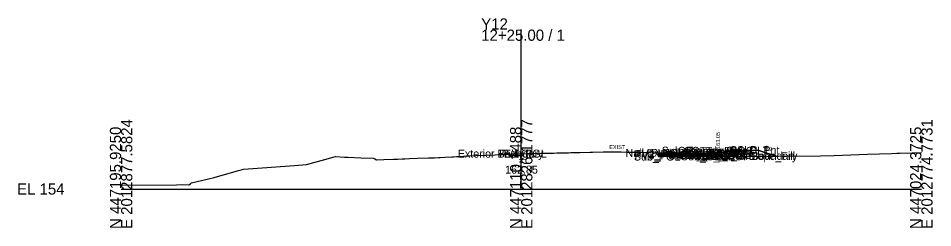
# Model space of a CAD drawing. Extents: x -26 to 1203, y -10 to 9542.
# Drawn here: x -25.7 to 202.8, y 4490.3 to 4542.7 of the extents above; entities that cross this region are included whole.
import ezdxf

# ---------------------------------------------------------------- set-up
doc = ezdxf.new("R2010")
doc.units = 0
for name, color, linetype in [('Default', 7, 'Continuous'), ('Exist Cross Section Cell', 7, 'Continuous'), ('Exist XS Center Line Elevation Label', 7, 'Continuous'), ('Exist XS Ground Line', 7, 'Continuous'), ('Prop CMT Conc Surface', 7, 'Continuous'), ('Prop CMT Concrete Structures', 7, 'Continuous'), ('Prop CMT Pvmt Course 1', 7, 'Continuous'), ('Prop CMT Pvmt Course 1 CG', 7, 'Continuous'), ('Prop CMT Pvmt Course 2', 7, 'Continuous'), ('Prop CMT Pvmt Course 3', 7, 'Continuous'), ('Prop CMT Pvmt Surface', 7, 'Continuous'), ('Prop CMT Slope Grass', 7, 'Continuous'), ('Prop CMT Subgrade Earthwork', 7, 'Continuous'), ('Prop XS Earthwork Shape', 7, 'Continuous'), ('Prop XS Hydro Elevations', 7, 'Continuous'), ('Prop XS SE Text', 7, 'Continuous'), ('Prop XS Side Slope Text', 7, 'Continuous'), ('Scratch_Level_0', 7, 'Continuous')]:
    doc.layers.add(name, color=color, linetype=linetype)

msp = doc.modelspace()

# ---------------------------------------------------------------- linework, layer by layer
at = {"layer": 'Exist Cross Section Cell'}
for p, q in [((100, 4500), (100, 4539.91)), ((0, 4500), (100, 4500)), ((100, 4500), (200, 4500))]:
    msp.add_line(p, q, dxfattribs=at)
at = {"layer": 'Exist XS Ground Line'}
msp.add_lwpolyline([(0, 4500.95), (13.82, 4501.09), (15.39, 4501.11), (16.89, 4501.03), (17.32, 4501.32), (17.62, 4501.54), (23.3, 4502.87), (29.36, 4504.62), (30.04, 4504.81), (30.61, 4505), (43.37, 4505.92), (46.33, 4506.17), (50.92, 4507.4), (53.59, 4508.1), (55.84, 4508), (56.7, 4507.96), (59.94, 4507.83), (63.05, 4507.71), (63.39, 4507.54), (63.83, 4507.32), (65.68, 4507.36), (68.05, 4507.46), (69.12, 4507.51), (70.26, 4507.55), (70.94, 4507.58), (72.12, 4507.62), (74.09, 4507.69), (76.79, 4507.78), (78.31, 4507.82), (79.35, 4507.89), (79.73, 4507.91), (80.9, 4507.97), (82.62, 4508.06), (83.06, 4508.08), (83.79, 4508.12), (84.9, 4508.17), (85.55, 4508.2), (88.56, 4508.35), (91.35, 4508.48), (93.48, 4508.58), (94.25, 4508.61), (95.8, 4508.67), (97.16, 4508.75), (97.59, 4508.77), (98.35, 4508.79), (99.46, 4508.83), (100.13, 4508.85), (101.29, 4508.88), (103.25, 4508.91), (104.93, 4508.95), (105.95, 4508.97), (106.76, 4508.99), (108.12, 4509.01), (108.87, 4509.03), (110, 4509.06), (111.78, 4509.1), (112.44, 4509.12), (112.88, 4509.13), (114.68, 4509.18), (117.24, 4509.23), (117.81, 4509.24), (120.49, 4509.29), (122.67, 4509.31), (123.43, 4509.31), (123.85, 4509.3), (124.95, 4509.28), (126.32, 4509.25), (127.53, 4509.23), (129.24, 4509.2), (130.43, 4509.17), (132.4, 4509.11), (134.22, 4509.05), (135.88, 4508.97), (136.62, 4509.41), (137.25, 4509.31), (137.84, 4509.22), (138.14, 4509.17), (140.34, 4508.87), (144.21, 4508.47), (147.2, 4508.21), (148.53, 4508.15), (148.95, 4508.14), (149.27, 4508.14), (153.82, 4508.16), (174.82, 4508.31), (178.17, 4508.41), (186.52, 4508.7), (192.55, 4508.89), (193.84, 4508.94), (194.61, 4508.98), (197.69, 4509.05), (200, 4509.13)], dxfattribs=at)
at = {"layer": 'Prop CMT Conc Surface'}
msp.add_lwpolyline([(147.17, 4509.12), (149.17, 4509.05), (149.17, 4509.55), (149.67, 4509.55)], dxfattribs=at)
at = {"layer": 'Prop CMT Concrete Structures'}
for points in [[(147.17, 4509.12), (149.17, 4509.05), (149.17, 4509.55), (149.67, 4509.55)], [(149.67, 4509.55), (149.67, 4508.55), (147.17, 4508.53)], [(147.17, 4508.53), (147.17, 4509.12)]]:
    msp.add_lwpolyline(points, dxfattribs=at)
at = {"layer": 'Prop CMT Pvmt Course 1'}
for points in [[(134.35, 4509.04), (147.17, 4509.12)], [(134.35, 4509.04), (134.35, 4509.04)], [(134.35, 4508.79), (134.35, 4509.04)], [(147.17, 4509.12), (147.17, 4508.87)], [(100, 4508.86), (100, 4508.86)], [(147.17, 4508.87), (134.35, 4508.79)]]:
    msp.add_lwpolyline(points, dxfattribs=at)
at = {"layer": 'Prop CMT Pvmt Course 1 CG'}
for points in [[(147.17, 4508.53), (150.17, 4508.55), (150.5, 4508.22)], [(147.17, 4508.2), (147.17, 4508.53)], [(150.5, 4508.22), (147.17, 4508.2)]]:
    msp.add_lwpolyline(points, dxfattribs=at)
at = {"layer": 'Prop CMT Pvmt Course 2'}
for points in [[(134.35, 4508.79), (147.17, 4508.87)], [(134.35, 4508.46), (134.35, 4508.79)], [(147.17, 4508.53), (134.35, 4508.46)], [(147.17, 4508.87), (147.17, 4508.53)]]:
    msp.add_lwpolyline(points, dxfattribs=at)
at = {"layer": 'Prop CMT Pvmt Course 3'}
for points in [[(134.35, 4508.46), (147.17, 4508.53)], [(134.35, 4508.13), (134.35, 4508.46)], [(147.17, 4508.2), (134.35, 4508.13)], [(147.17, 4508.53), (147.17, 4508.2)]]:
    msp.add_lwpolyline(points, dxfattribs=at)
at = {"layer": 'Prop CMT Pvmt Surface'}
msp.add_lwpolyline([(134.35, 4509.04), (147.17, 4509.12)], dxfattribs=at)
at = {"layer": 'Prop CMT Slope Grass'}
msp.add_lwpolyline([(149.67, 4509.55), (159.17, 4509.74), (163.68, 4508.23)], dxfattribs=at)
at = {"layer": 'Prop CMT Subgrade Earthwork'}
for points in [[(134.35, 4508.13), (134.35, 4509.04)], [(147.17, 4508.2), (150.5, 4508.22), (151.87, 4509.59)], [(134.35, 4508.13), (147.17, 4508.2)], [(147.17, 4508.2), (134.35, 4508.13)]]:
    msp.add_lwpolyline(points, dxfattribs=at)
at = {"layer": 'Prop XS Earthwork Shape'}
for points in [[(134.35, 4509.04), (135.88, 4508.97), (136.01, 4509.05), (138.9, 4509.07), (140.34, 4508.87), (144.21, 4508.47), (147.2, 4508.21), (147.43, 4508.2), (147.17, 4508.2), (134.35, 4508.13)], [(137.25, 4509.31), (137.84, 4509.22), (138.14, 4509.17), (138.9, 4509.07), (136.01, 4509.05), (136.62, 4509.41)], [(149.27, 4508.14), (153.82, 4508.16), (163.68, 4508.23), (159.17, 4509.74), (151.87, 4509.59), (150.5, 4508.22), (147.43, 4508.2), (148.53, 4508.15), (148.95, 4508.14)]]:
    msp.add_lwpolyline(points, close=True, dxfattribs=at)

# ---------------------------------------------------------------- texts
at = {"layer": 'Default'}
msp.add_text('-', height=0.0001, dxfattribs=at).set_placement((0, 4500))
at = {"layer": 'Exist Cross Section Cell'}
for s, p in [('Y12', (90, 4539.91)), ('12+25.00 / 1', (90, 4537.11)), ('EL 154', (-26, 4498.6))]:
    msp.add_text(s, height=2.8, dxfattribs=at).set_placement(p)
for s, p in [('E 2012877.5824', (2.8, 4490)), ('E 2012826.1777', (102.8, 4490)), ('E 2012774.7731', (202.8, 4490)), ('N 447195.9250', (0, 4490)), ('N 447110.1488', (100, 4490)), ('N 447024.3725', (200, 4490))]:
    msp.add_text(s, height=2.8, rotation=90, dxfattribs=at).set_placement(p)
at = {"layer": 'Exist XS Center Line Elevation Label'}
msp.add_text('162.85', height=2, dxfattribs=at).set_placement((95.98, 4503.85))
at = {"layer": 'Prop XS Hydro Elevations'}
msp.add_text('163.05', height=1, rotation=90, dxfattribs=at).set_placement((149.67, 4510.05))
at = {"layer": 'Prop XS SE Text'}
msp.add_text('EXIST', height=1, rotation=0.314, dxfattribs=at).set_placement((122, 4509.98))
at = {"layer": 'Prop XS Side Slope Text'}
msp.add_text('3:1', height=1, rotation=341.5647, dxfattribs=at).set_placement((160.81, 4509.98))
at = {"layer": 'Scratch_Level_0'}
for s, p in [('Exterior Boundary', (84.14, 4507.86)), ('PV1_PGL', (94.47, 4507.86)), ('EX CL', (95.67, 4507.86)), ('Null Ex EOP', (126.05, 4508.04)), ('Sub_PGL', (128.16, 4507.13)), ('PV2_PGL', (128.26, 4507.79)), ('PV3_PGL', (128.26, 4507.46)), ('PV1', (132.43, 4508.04)), ('Sub_Trench_Out_DLT', (135.13, 4508.59)), ('CG_Top_Face', (139.12, 4508.55)), ('CG1_Shelf_Out', (139.41, 4507.55)), ('CG_Bot_IE', (139.77, 4507.53)), ('Sub_OEOT', (139.94, 4507.2)), ('CG_Top_Gut', (140.1, 4508.05)), ('PV2_OEOT', (140.03, 4507.87)), ('PV3_OEOT', (140.03, 4507.53)), ('CG_Top_BOC', (140.64, 4508.55)), ('CG_Bot_BOC', (140.68, 4507.55)), ('PV1_OEOT', (140.6, 4508.12)), ('Sub_OEOP', (143.3, 4507.22)), ('Exterior Boundary', (147.61, 4507.3)), ('CSLP_Pnt', (152.03, 4508.74)), ('Slope_Fill', (156.68, 4507.3))]:
    msp.add_text(s, height=2, dxfattribs=at).set_placement(p)

doc.saveas('drawing.dxf')
